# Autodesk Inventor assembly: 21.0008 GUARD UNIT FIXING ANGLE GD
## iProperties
Created: 2009-01
Part Number: 21.0008 GUARD UNIT FIXING ANGLE GD
Document SubType Name: Assembly
Designer: Administrator
Author: Administrator
